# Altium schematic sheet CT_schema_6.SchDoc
size 372 x 245 mm
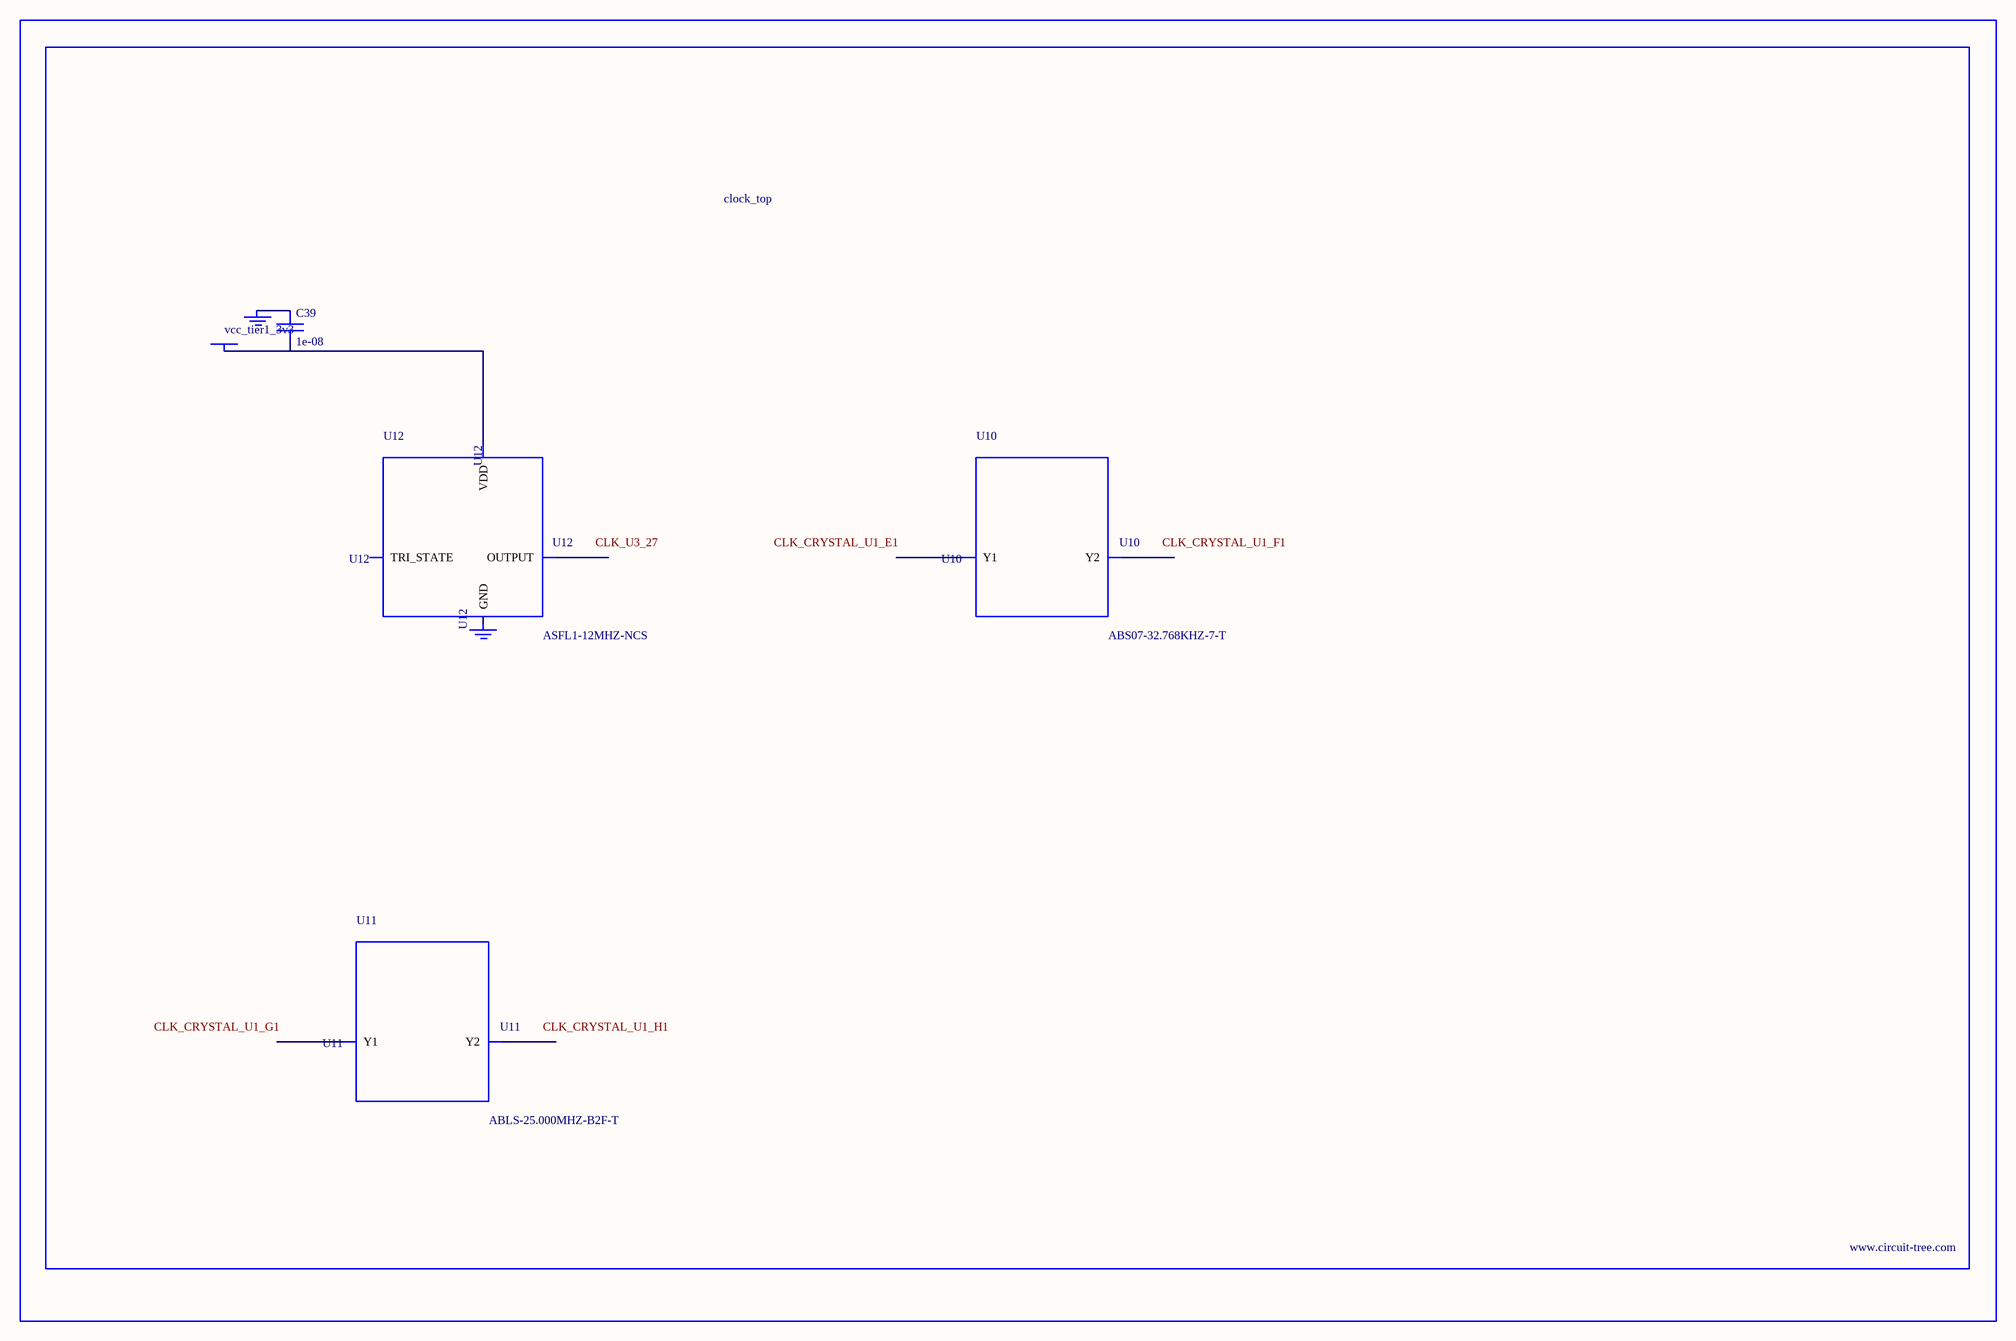
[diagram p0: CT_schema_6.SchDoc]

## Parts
BORDER5  (no value)
C39  1e-08  [C0402]
GND_INSTANCE_5_0  (no value)
GND_INSTANCE_5_1  (no value)
POWER_INSTANCE_5_0  vcc_tier1_3v3
U10  ABS07-32.768KHZ-7-T  [ABS07-32.768KHZ-7-T]
U11  ABLS-25.000MHZ-B2F-T  [ABLS-25.000MHZ-B2F-T]
U12  ASFL1-12MHZ-NCS  [ASFL1]

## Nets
NetC39_1: C39.1 GND_INSTANCE_5_0.0(GND)
NetC39_2: C39.2 POWER_INSTANCE_5_0.0(PWR) U12.4(VDD)

Not connected (* = marked no-connect by the designer): GND_INSTANCE_5_1 0(GND); U10 1(Y1) 2(Y2); U11 1(Y1) 2(Y2); U12 1(TRI_STATE) 2(GND) 3(OUTPUT)

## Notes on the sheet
- Labels drawn without touching a wire or pin: CLK_CRYSTAL_U1_E1, CLK_CRYSTAL_U1_F1, CLK_CRYSTAL_U1_G1, CLK_CRYSTAL_U1_H1, CLK_U3_27

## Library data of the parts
BORDER5 = BORDER_PAGE5
C39 = C0402C103K3RAC
GND_INSTANCE_5_0 GND_INSTANCE_5_1 = GND
POWER_INSTANCE_5_0 = PWR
